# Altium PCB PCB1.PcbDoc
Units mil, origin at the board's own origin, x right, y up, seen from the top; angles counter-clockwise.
Board outline 3785 x 5141 mil, 2 copper layers (Top Layer, Bottom Layer); 51 components, 34 nets, 186 pads, 22 vias.
Unrouted connection lines stored in the file: 92.
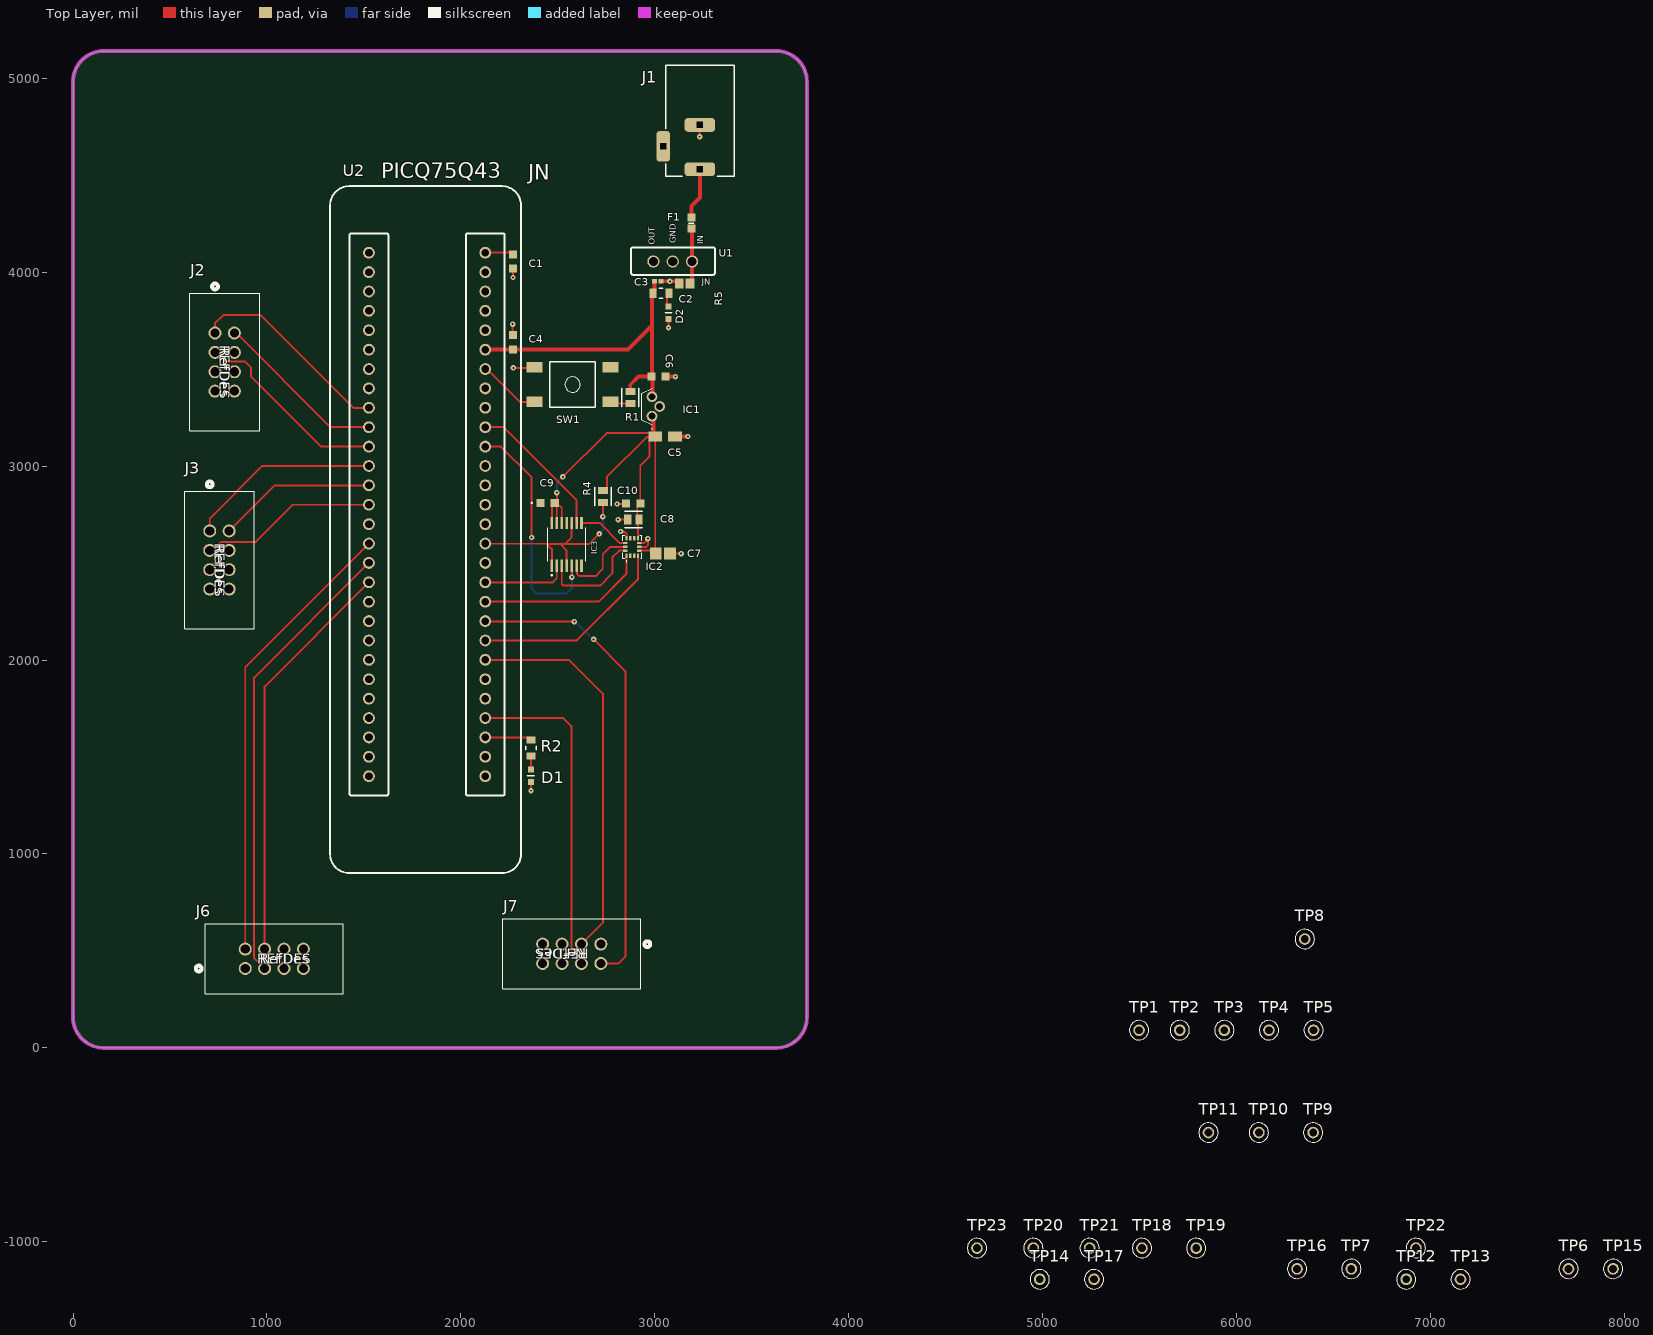
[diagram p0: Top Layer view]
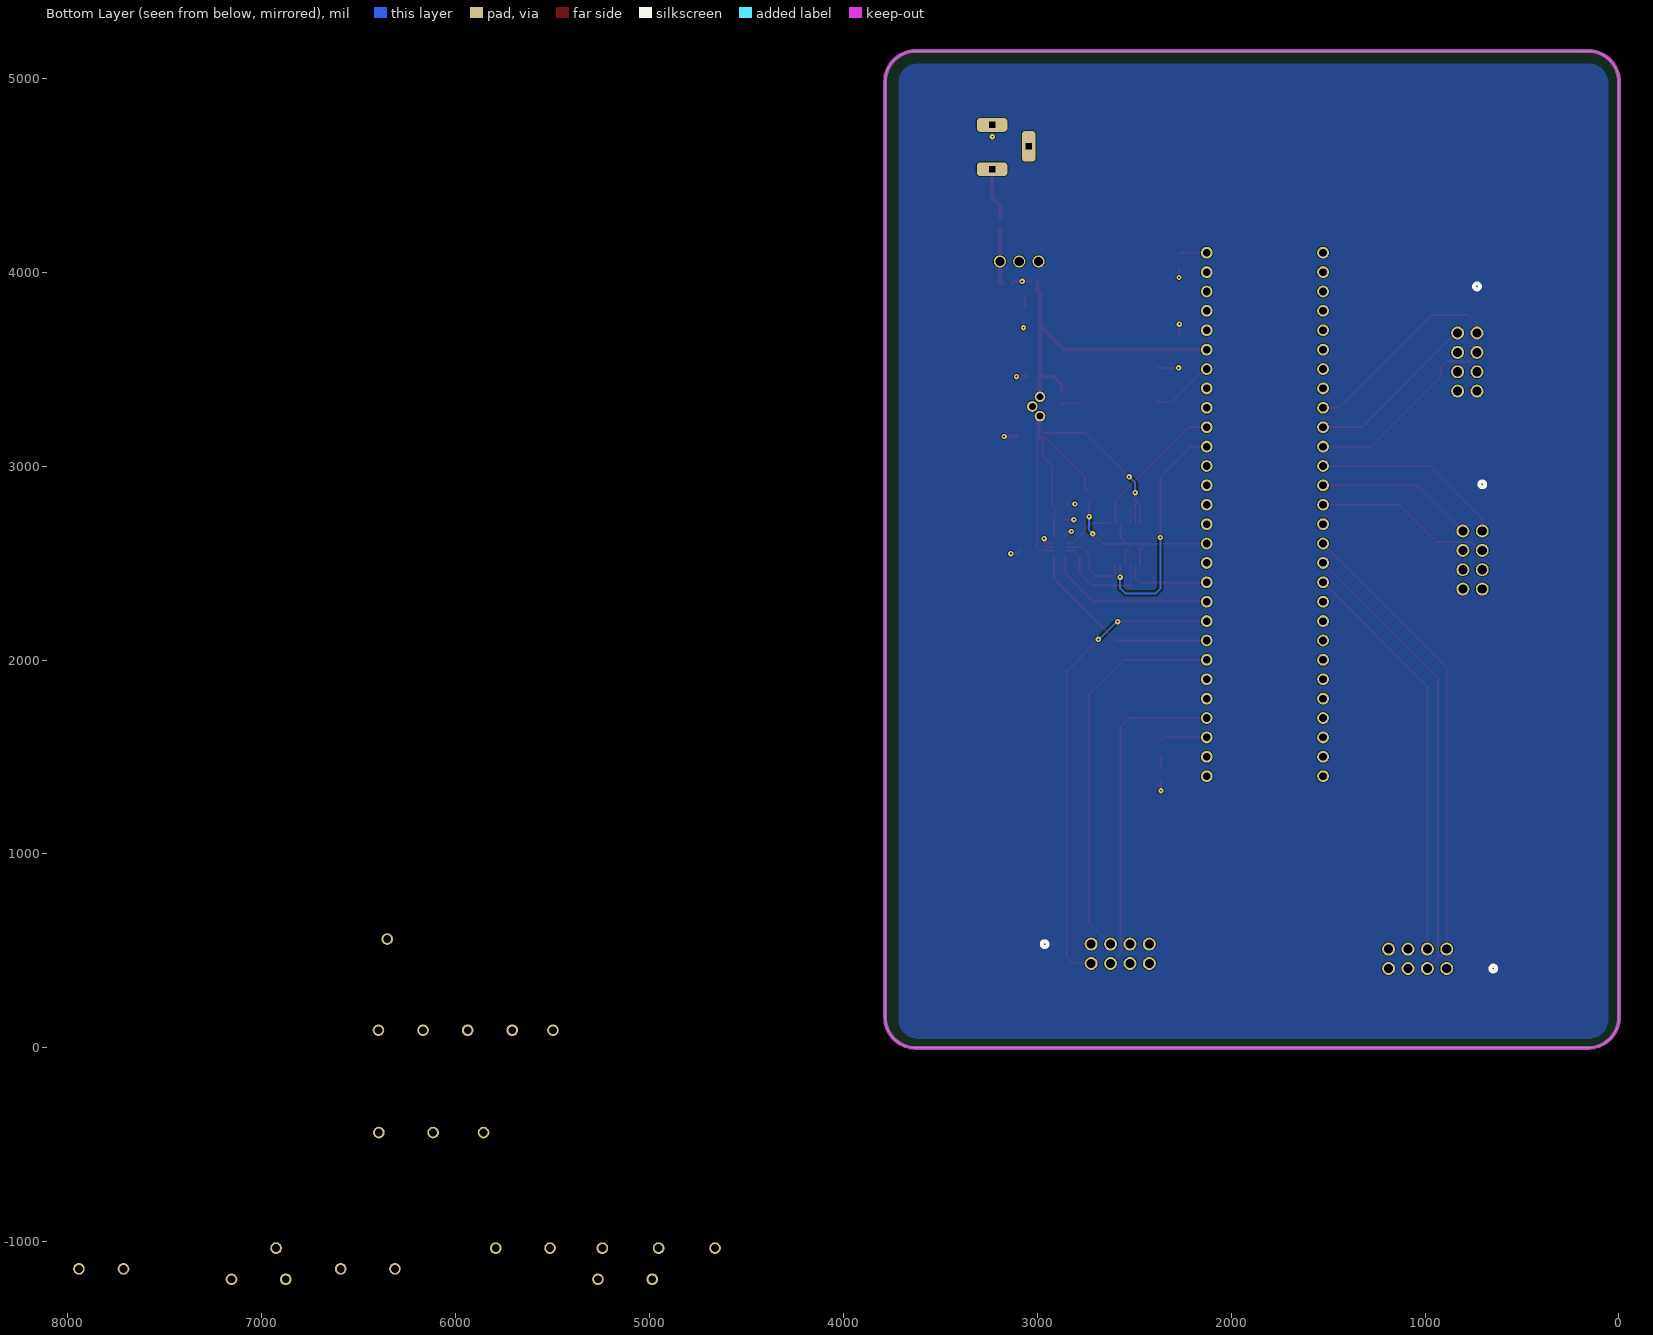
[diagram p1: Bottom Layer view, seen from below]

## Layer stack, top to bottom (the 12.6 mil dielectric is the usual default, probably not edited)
Top Solder: solder mask 0.4, Solder Resist, Dk 3.5
Top Layer: signal copper 1.4
Dielectric 1: dielectric 12.6, FR-4, Dk 4.8
Bottom Layer: signal copper 1.4
Bottom Solder: solder mask 0.4, Solder Resist, Dk 3.5

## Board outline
0,157.48 0,4983.52 cw(c157.48,4983.52) 157.48,5141 3627.52,5141 cw(c3627.52,4983.52) 3785,4983.52 3785,157.48 cw(c3627.52,157.48) 3627.52,0 157.48,0 cw(c157.48,157.48)

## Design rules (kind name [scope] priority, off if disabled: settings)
Clearance PTH_Hole_to_Copper [IsPad and (HoleSize > 0) vs IsPad and (HoleSize > 0)] p1: gap=4 ignorepadtopadclearanceinfootprint=FALSE except(3: SMDPad-Fill SMDPad-Poly SMDPad-Region; 4.02: Via-Hole; 11.81: Fill-Hole Poly-Hole Region-Hole; 13.78: Arc-Hole Track-Hole)
Clearance Via_Hole_to_Copper [IsVia vs IsVia] p2: gap=4 ignorepadtopadclearanceinfootprint=FALSE except(3: SMDPad-Fill SMDPad-Poly SMDPad-Region; 4.02: Arc-Arc Arc-Track Track-Track Via-Fill Via-Poly Via-Region Via-Hole; 7.87: Arc-Hole Track-Hole Fill-Hole Poly-Hole Region-Hole)
Clearance Same_Net_Track [IsTrack vs IsTrack] p3: gap=4 ignorepadtopadclearanceinfootprint=FALSE except(3: SMDPad-Fill SMDPad-Poly SMDPad-Region; 4.02: Via-Hole; 9.84: Arc-Arc Arc-Track Track-Track)
Clearance [All] p4: gap=4 ignorepadtopadclearanceinfootprint=FALSE except(2: Text-Text; 3: SMDPad-Fill SMDPad-Poly SMDPad-Region; 4.02: SMDPad-Text THPad-Text Via-Hole; 5.91: SMDPad-SMDPad; 10: Track-Poly)
ComponentClearance [All] p1: gap=10 collisioncheckmode=3 verticalgap=20 showdistances=FALSE
HoleSize [All] p1: absolutevalues=TRUE maxlimit=248.03 minlimit=5.91 maxpercent=80.000 minpercent=20.000
HoleToHoleClearance Via_Hole_to_Hole [IsVia vs IsVia] p1: gap=7.87 allowstackedmicrovias=TRUE
HoleToHoleClearance Pad_Hole_to_Hole [IsPad vs IsPad] p2: gap=17.72 allowstackedmicrovias=TRUE
MinimumAnnularRing PTH_Annular_Ring [IsPad and (HoleSize > 0)] p1: minimumring=7.87
MinimumAnnularRing Via_Annular_Ring [IsVia] p2: minimumring=2.95
MinimumSolderMaskSliver [All] p1: minsoldermaskwidth=3.94
PolygonConnect [All] p1: connectstyle=Direct reliefconductorwidth=10 reliefentries=4 polygonreliefangle="90 Angle" airgapwidth=10
RoutingVias [All] p1: holewidth=10 width=28 viastyle="Through Hole" minholewidth=5.91 minwidth=11.81 maxholewidth=248.03 maxwidth=259.84
SilkToSolderMaskClearance [IsPad] p1: minsilkscreentomaskgap=5.91 clearancetoexposedcopper=TRUE
SolderMaskExpansion [All] p1: expansion=0 istentingtop=FALSE
SupplyNets "Schematic Supply Nets_8" [InNet('+9V')] p1: voltage=0.000
SupplyNets "Schematic Supply Nets_7" [InNet('+5V_IN')] p2: voltage=0.000
SupplyNets "Schematic Supply Nets_6" [InNet('+5V_BUS')] p3: voltage=0.000
SupplyNets "Schematic Supply Nets_4" [InNet('+3V3')] p4: voltage=0.000
SupplyNets "Schematic Supply Nets_2" [InNet('GND')] p5: voltage=0.000
UnRoutedNet [All] p1: checkbadconnections=TRUE
Width [All] p1: maxlimit=20 minlimit=3.94 preferedwidth=10
24 further rules are at their usual default settings.

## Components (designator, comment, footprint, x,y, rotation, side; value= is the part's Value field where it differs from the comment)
C1 ".1uF 25V" C2012_Commercial 2270,4056 r90 top
C2 ".33uF 35V" CAPC2113X120X50LL20T30 3154,3942 r0 top
C3 ".1uF 25V" CAPC1005X56X25NL10T15 3015.68,3954 r180 top
C4 ".1uF 25V" C2012_Commercial 2269,3639 r270 top
C5 "2.2uF 35V" CAPPM3216X180N 3054,3154 r0 top
C6 "1uF 25V" C2012_Commercial 3020,3463 r180 top
C7 "10nF 50V" CAPC2013X94X50ML20T25 3042,2550 r180 top
C8 "2.2uF 16V" FP-C0805C225K4RACAUTO-MFG 2890,2725 r180 top
C9 ".1uF 25V" C2012_Commercial 2448,2811 r0 top
C10 ".1uF 25V" C2012_Commercial 2889,2807 r0 top
D1 "LED_B" FP-SML-D12-MFG 2361,1404 r90 top
D2 "LED_Y" FP-SML-D12-MFG 3071,3792 r90 top
F1 "1A_FUSE" FUSC1608X61N 3189,4254 r270 top
IC1 "LP2950-33LPRE3" TL431CLPM 2986,3258 r90 top
IC2 "ICM-42688-P" IIM42352 2884,2584 r90 top
IC3 "SN74LVC125APWR" SN74LVC125APWR 2546,2597 r0 top
J1 "694108301002" 694108301002 3233,4781.65 r180 top
J2 "702460801" CONN_7024608xx_MOL 732,3687 r270 top
J3 "702460801" CONN_7024608xx_MOL 705,2666 r270 top
J6 "702460801" CONN_7024608xx_MOL 888,409 r0 top
J7 "702460801" CONN_7024608xx_MOL 2722,535 r180 top
R1 "10k .125W" FP-CRGCQ0805-IPC_C 2874,3354 r90 top value=10KΩ
R2 "562R .125W" FP-RT0805-MFG 2362,1547 r90 top value=562Ω
R4 "10k .125W" FP-CRGCQ0805-IPC_C 2733,2844 r90 top value=10KΩ
R5 "562R  .125W" FP-RT0805-MFG 3032,3892 r180 top value=562Ω
SW1 "Button" FP-1301_9320-MFG 2576,3421 r0 top
TP1 "5001" KEYSTONE_5001 5498,91 r0 top
TP2 "5001" KEYSTONE_5001 5708,91 r0 top
TP3 "5001" KEYSTONE_5001 5938,91 r0 top
TP4 "5001" KEYSTONE_5001 6168,91 r0 top
TP5 "5001" KEYSTONE_5001 6398,91 r0 top
TP6 "5001" KEYSTONE_5001 7713,-1140 r0 top
TP7 "5001" KEYSTONE_5001 6593,-1140 r0 top
TP8 "5001" KEYSTONE_5001 6353,561 r0 top
TP9 "5001" KEYSTONE_5001 6396,-437 r0 top
TP10 "5001" KEYSTONE_5001 6116,-437 r90 top
TP11 "5001" KEYSTONE_5001 5856,-437 r0 top
TP12 "5001" KEYSTONE_5001 6876,-1194 r90 top
TP13 "5001" KEYSTONE_5001 7156,-1194 r90 top
TP14 "5001" KEYSTONE_5001 4986,-1194 r90 top
TP15 "5001" KEYSTONE_5001 7943,-1140 r90 top
TP16 "5001" KEYSTONE_5001 6313,-1140 r90 top
TP17 "5001" KEYSTONE_5001 5266,-1194 r90 top
TP18 "5001" KEYSTONE_5001 5513,-1033 r90 top
TP19 "5001" KEYSTONE_5001 5793,-1033 r90 top
TP20 "5001" KEYSTONE_5001 4953,-1033 r90 top
TP21 "5001" KEYSTONE_5001 5243,-1033 r0 top
TP22 "5001" KEYSTONE_5001 6926,-1033 r90 top
TP23 "5001" KEYSTONE_5001 4662,-1033 r90 top
U1 "LM7805_JN" LM7805_JN 3093,4056 r180 top
U2 "PIC18F57Q43" PIC1857Q43_JN 1326,901 r0 top

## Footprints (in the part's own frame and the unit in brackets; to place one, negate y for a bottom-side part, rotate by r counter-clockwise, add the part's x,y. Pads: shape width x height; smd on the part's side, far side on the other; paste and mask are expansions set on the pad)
694108301002 [mm] "DC Power Jack Right Angled(6.4)"
  rrect50% 4x1.8 hole 0.8 square: 1(0,6.35) 2(0,0.55)
  rrect50% 1.8x4 hole 0.8 square: 3(4.8,3.35)
  silkscreen extent -4.5,-7.25 4.5,7.25, body extent -4.5,-7.25 5,7.25, height 10.75
C2012_Commercial [mm]
  rect 1.05x1.05 smd: 1(-0.925,0) 2(0.925,0)
  body extent -0.96,-0.8 1.04,0.8, height 1.25
CAPC1005X56X25NL10T15 [mm] "Chip Capacitor, 2-Leads, Body 1.00x0.50mm, IPC Medium Density"
  rect 0.68x0.64 smd: 1(-0.44,0) 2(0.44,0)
  body extent -0.55,-0.3 0.55,0.3, height 0.56
CAPC2013X94X50ML20T25 [mm] "Chip Capacitor, 2-Leads, Body 2.01x1.25mm, IPC Low Density"
  rect 1.55x1.55 smd: 1(-0.925,0) 2(0.925,0)
  body extent -1.1,-0.72 1.11,0.72, height 0.94
CAPC2113X120X50LL20T30 [mm] "Chip Capacitor, 2-Leads, Body 2.05x1.25mm, IPC High Density"
  rect 1.15x1.35 smd: 1(-0.7,0) 2(0.7,0)
  body extent -1.13,-0.72 1.12,0.72, height 1.2
CAPPM3216X180N [mm]
  rect 1.8x1.3 smd: 1(-1.3,0) 2(1.3,0)
  body extent -1.6,-0.82 1.6,0.82, height 1.8
CONN_7024608xx_MOL [mil]
  round 67 / inner round 60 / far side round 67 hole 47 paste-99999 mask+0: 1(0,0) 2(0,100) 3(100,0) 4(100,100) 5(200,0) 6(200,100) 7(300,0) 8(300,100)
  silkscreen extent -255,-130 505,230
FP-1301_9320-MFG [mm]
  rect 2.1x1.4 smd paste+0 mask+0: 1(-5,2.25) 2(5,2.25) 3(-5,-2.25) 4(5,-2.25)
  silkscreen extent -3,-3 3,3, body extent -6.15,-3.1 6.15,3.1, height 0.25
FP-C0805C225K4RACAUTO-MFG [mm]
  rect 0.95x1.35 smd paste+0 mask+0: 1(-0.75,0) 2(0.75,0)
  silkscreen extent -1.15,-1.07 1.15,1.07, body extent -1.4,-0.85 1.4,0.85, height 0.25
FP-CRGCQ0805-IPC_C [mil]
  rect 35.67x51.57 smd paste+0 mask+0: 1(-30.55,0) 2(30.55,0)
  silkscreen extent -48,-43 48,43, body extent -52,-31 52,31, height 10
FP-RT0805-MFG [mm]
  rect 0.9x1.2 smd paste+0 mask+0: 1(-1.05,0) 2(1.05,0)
  silkscreen extent -0.23,-0.67 0.23,0.67, body extent -1.6,-0.77 1.6,0.77, height 0.25
FP-SML-D12-MFG [mm]
  rect 0.8x0.8 smd paste+0 mask+0: 1(-0.825,0) 2(0.825,0)
  silkscreen extent 0,-0.45 0,0.45, body extent -1.33,-0.55 1.33,0.55, height 0.25
FUSC1608X61N [mm]
  rect 1x1.02 smd: 1(-0.72,0) 2(0.72,0)
  silkscreen extent 0,-0.33 0,0.33, body extent -0.79,-0.43 0.79,0.43, height 0.61
IIM42352 [mm]
  rect 0.6x0.3 smd: 1(-1.15,0.75) 2(-1.15,0.25) 3(-1.15,-0.25) 4(-1.15,-0.75) 8(1.15,-0.75) 9(1.15,-0.25) 10(1.15,0.25) 11(1.15,0.75)
  rect 0.3x0.6 smd: 5(-0.5,-0.9) 6(0,-0.9) 7(0.5,-0.9) 12(0.5,0.9) 13(0,0.9) 14(-0.5,0.9)
  silkscreen extent -1.95,-1.25 1.5,1.25, body extent -1.5,-1.25 1.5,1.25, height 0.9
KEYSTONE_5001 [mm]
  round 1.53 hole 1.02: TP(0,0)
  silkscreen extent -1.27,-1.27 1.27,1.27, body extent -1.27,-1.27 1.27,1.27, height 4.57
LM7805_JN [mm]
  round 1.6 hole 1.2 paste-2539.97 mask+0.1: 1(-2.54,0) 2(0,0) 3(2.54,0)
  silkscreen extent -5.54,-1.85 5.46,1.75
PIC1857Q43_JN [mm]
  round 1.55 hole 1 paste-2539.97 mask+0.1: 1(5.08,81.28) 2(5.08,78.74) 3(5.08,76.2) 4(5.08,73.66) 5(5.08,71.12) 6(5.08,68.58) 7(5.08,66.04) 8(5.08,63.5) 9(5.08,60.96) 10(5.08,58.42) 11(5.08,55.88) 12(5.08,53.34) 13(5.08,50.8) 14(5.08,48.26) 15(5.08,45.72) 16(5.08,43.18) 17(5.08,40.64) 18(5.08,38.1) 19(5.08,35.56) 20(5.08,33.02) 21(5.08,30.48) 22(5.08,27.94) 23(5.08,25.4) 24(5.08,22.86) 25(5.08,20.32) 26(5.08,17.78) 27(5.08,15.24) 28(5.08,12.7) 29(20.32,81.28) 30(20.32,78.74) 31(20.32,76.2) 32(20.32,73.66) 33(20.32,71.12) 34(20.32,68.58) 35(20.32,66.04) 36(20.32,63.5) 37(20.32,60.96) 38(20.32,58.42) 39(20.32,55.88) 40(20.32,53.34) 41(20.32,50.8) 42(20.32,48.26) 43(20.32,45.72) 44(20.32,43.18) 45(20.32,40.64) 46(20.32,38.1) 47(20.32,35.56) 48(20.32,33.02) 49(20.32,30.48) 50(20.32,27.94) 51(20.32,25.4) 52(20.32,22.86) 53(20.32,20.32) 54(20.32,17.78) 55(20.32,15.24) 56(20.32,12.7)
  silkscreen extent 0,0 25,90
SN74LVC125APWR [mm]
  rect 0.35x1.6 smd: 1(-1.95,-2.8) 2(-1.3,-2.8) 3(-0.65,-2.8) 4(0,-2.8) 5(0.65,-2.8) 6(1.3,-2.8) 7(1.95,-2.8) 8(1.95,2.8) 9(1.3,2.8) 10(0.65,2.8) 11(0,2.8) 12(-0.65,2.8) 13(-1.3,2.8) 14(-1.95,2.8)
  silkscreen extent -2.5,-4.1 2.5,2.2, body extent -2.5,-3.2 2.5,3.2, height 1.13
TL431CLPM [mm]
  round 1.4 hole 0.9: 1(0,0) 2(1.27,-1) 3(2.54,0)
  silkscreen extent -1.71,-0.05 3.67,1.35, body extent -1.13,-2.22 3.69,1.46, height 9.91

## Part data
C1 C4 C9 C10: library part C2012X7R1V105K085AB, "Capacitor / C0805C104J3RACTU / 0805", Manufacturer_Name=TDK, Mouser Part Number=810-C2012X7R1V105K0B
C2: library part CMP-2007-04070-1, "TAJR334K035RNJ", Manufacturer="AVX Interconnect / Elco"
C3: library part CMP-1034-02072-2, "04023D104KAT2A", Manufacturer="AVX Interconnect / Elco"
C5: library part TPSA225K035R1500, "Capacitor Polarised / 1.5ohm ESR for Output Requirement / Tantalum / 1206", Manufacturer_Name="Kyocera AVX", Mouser Part Number=581-TPSA225K035R1500
C6: library part C2012X7R1V105K085AB, "Capacitor / C0805C105K3RACTU / 0805", Manufacturer_Name=TDK, Mouser Part Number=810-C2012X7R1V105K0B
C7: library part CMP-2007-04453-1, "KGM21NR71H103KT /  / 0805", Manufacturer="AVX Interconnect / Elco", Part Number=0805YC103MAT2A
C8: library part CMP-2007-03267-2, "CAP CER 2.2UF 16V X7R 0805 / C0805C225K4RACAUTO", Capacitance=2.2uF, Case Code (Imperial)=0805, Case Code (Metric)=2012, Dielectric=X7R, Dielectric Material=Ceramic, Max Operating Temperature=125°C, Min Operating Temperature=-55°C, Package Quantity=1, Ratings=AEC-Q200, Tolerance=10%, Voltage Rating=16V
D1: library part CMP-08952-000023-1, "SMLD12BN1WT86 /  / BLUE LED 0603", Colour=Yellow, Forward Current=20mA, Forward Voltage=2.2V, Manufacturer=Rohm, Manufacturer Part Number=SML-D12Y8WT86, Package=SML-D12, Power Dissipation=54mW, Reverse Voltage=5V, Temperature="-40°C to +85°C", Temperature Range High=+85°C, Temperature Range Low=-40°C
D2: library part CMP-08952-000023-1, "LED YELLOW DIFFUSED 0603 SMD / SML-D12Y8WT86", Colour=Yellow, Forward Current=20mA, Forward Voltage=2.2V, Manufacturer=Rohm, Manufacturer Part Number=SML-D12Y8WT86, Package=SML-D12, Power Dissipation=54mW, Reverse Voltage=5V, Temperature="-40°C to +85°C", Temperature Range High=+85°C, Temperature Range Low=-40°C
F1: library part 0438001.A, "Fuse", Manufacturer_Name=LITTELFUSE
IC1: "Integrated Circuit", Manufacturer_Name="Texas Instruments", Mouser Part Number=595-LP2950-33LPRE3
IC2: "Integrated Circuit", Manufacturer_Name=TDK, Mouser Part Number=410-ICM-42688-P
IC3: "Integrated Circuit", Manufacturer_Name="Texas Instruments", Mouser Part Number=595-SN74LVC125APWR
J1: library part CMP-1502-00190-4, "DC Power Jack Connector WR-DC, Male, Right Angled, THT, 5 A, 24 V", Color=Black, Current Rating=5A, Flammability Rating="UL94 V-0", Insulation Resistance=100MΩ, Max Operating Temperature=85°C, Min Operating Temperature=-40°C, Operating Supply Voltage=24V, Voltage Rating=30V
J2 J3 J6 J7: "2.54mm Pitch C-Grid Header, Low Profile, Dual Row, Vertical, Shrouded, 8  Circuits, 0.38Âµm Gold (Au) Selective Plating", Manufacturer_Name="Molex Connector Corporation"
R1 R4: library part CMP-03211-002989-1, "CRGCQ0805J10K", Ambient Temperature Range High=+70°C, Manufacturer="TE Connectivity", Package=CRGCQ0805, Power Rating=0.125W, Resistance=10KΩ, Temperature="-55°C to +155°C", Temperature Coefficient=±100ppm/°C, Temperature Range High=+155°C, Temperature Range Low=-55°C, Tolerance=0.05, Voltage Rating=150V
R2 R5: library part CMP-03412-035770-1, "RES SMD 562 OHM 1% 1/8W 0805 / RT0805FRD07562RL", Manufacturer=Yageo, Manufacturer Part Number=RT0805FRD07562RL, Package=RT0805, Power Rating=0.125W, Resistance=562Ω, Temperature="-55°C to +155°C", Temperature Coefficient="25 ppm/°C", Temperature Range High=+155°C, Temperature Range Low=-55°C, Tolerance=0.0001, Voltage Rating=150V
SW1: library part CMP-26321-000001-1, "SWITCH TACTILE SPST-NO 0.05A 12V / 1301.9320", Contact Current Rating=50mA, Contact Resistance=100mΩ, Manufacturer=Schurter, Manufacturer Part Number=1301.9320, Operating Force=1.6N, Package=0, Temperature="-20°C to +70°C", Temperature Range High=+70°C, Temperature Range Low=-20°C, Voltage Rating Dc=12V
TP1 TP2 TP3 TP4 TP5 TP6 TP7 TP8 TP9 TP10 TP11 TP12 TP13 TP14 TP15 TP16 TP17 TP18 TP19 TP20 TP21 TP22 TP23: library part CMP-003-000000-1, Package=None
U1: library part LM7805_JN_1
U2: library part PIC18F57Q43_JN

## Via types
v1: diameter 28, hole 10, Top Layer to Bottom Layer, 22 vias

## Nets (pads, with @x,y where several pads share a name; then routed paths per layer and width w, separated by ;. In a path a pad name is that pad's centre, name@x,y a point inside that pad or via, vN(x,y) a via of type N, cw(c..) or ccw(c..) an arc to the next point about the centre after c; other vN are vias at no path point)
+3V3: C5.1 C7.2 C8.1 C9.2 C10.2 IC1.1 IC2.5 IC2.8 IC3.12 IC3.13 IC3.14 R4.2 TP6.TP | length 3224.6
  Top Layer w10: 2122,2401 2475,2401 2494.82,2420.82 2494.82,2486.76 ; IC3.14 2469.23,2794.81 C9.2@2485.42,2811 ; C9.2@2493.82,2801.6 C9.2 2495,2821.58 v1(2495,2864) ; IC3.13 2494.82,2801.6 2500.5,2795.91 2511.09,2795.91 2520.41,2786.59 IC3.12 ; v1(2526,2945) 2752,3171 C5.1@2971.83,3171 ; R4.2 2740.95,2874.55 2753.78,2887.39 2753.78,2944.78 2958.36,3149.36 2988.99,3149.36 2993.63,3154 C5.1 ; C8.1@2909.75,2748 2909.75,2791.33 C10.2 2925.42,3002.42 2972.39,3049.39 2972.39,3133.41 C5.1@2980.6,3141.63 ; IC2.8 C8.1@2913.53,2725 ; IC2.5 2987.9,2564.31 C7.2@2996.58,2573 ; C5.1@2992.98,3154 C5.1@2980.6,3141.63 ; C7.2@3002.82,2576 C5.1 ; C5.1@2980.6,3141.63 2990.45,3141.63 C5.1
  Top Layer w20: IC1.1@2993.63,3266 2993.63,3163.19 C5.1
  Bottom Layer w10: v1@2496,2864 2495,2865 2495,2914 v1(2526,2945)
+5V_BUS: C1.2 TP15.TP U2.29 | length 147.6
  Top Layer w10: U2.29 2261.42,4101 C1.2
+5V_IN: C3.2 C4.2 C6.2 IC1.3 R1.2 R5.2 U1.3 U2.34 | length 1673.1
  Top Layer w20: U2.34 2862.62,3601 2986.62,3725 ; R1.2 2874,3420 2917,3463 C6.2 ; IC1.3@2993.63,3366 2988.61,3371.02 2988.61,3457.98 C6.2 ; C3.2 2998.35,3899.69 R5.2 2986.62,3887.96 2986.62,3725 ; C6.2 2986.62,3466.04 2986.62,3725
+9V: F1.1 J1.1 TP22.TP | length 267.5
  Top Layer w20: F1.1 3189,4341.53 3233,4385.53 J1.1
BUT_D: SW1.3 TP23.TP U2.35 | length 323.3
  Top Layer w10: U2.35 2136,3501 2305,3332 2378.73,3332 SW1.3
GND: C1.1 C2.1 C3.1 C4.1 C5.2 C6.1 C7.1 C8.2 C9.1 C10.1 D1.1 D2.1 IC1.2 IC2.6 IC2.7 IC2.11 IC3.7 J1.2 J2.8 J3.8 J6.8 J7.8 SW1.1 TP7.TP TP8.TP TP14.TP TP16.TP TP17.TP U1.2 U2.15 U2.24 U2.30 U2.33 U2.43 U2.52 | length 948.5
  Top Layer w10: v1(2267,3733) 2267,3677.42 C4.1 ; v1(2269,3973) 2269,4018.58 C1.1 ; v1(2271,3507) 2376.57,3507 SW1.1 ; D1.1 2362,1370.52 v1(2362,1326) ; v1@2800,2805 2850.58,2805 C10.1 ; v1(2811,2724) 2859.47,2724 C8.2 ; v1(2824,2663) 2827.44,2659.56 2846.44,2659.56 2854.47,2651.53 IC2.11 ; IC2.6 2957,2584 2965,2592 v1(2965,2626) 2942.69,2603.69 IC2.7 ; v1(3071.09,3714.09) D2.1@3071.09,3759.43 ; C7.1@3078.42,2572 3101.42,2549 v1(3136,2549) ; v1(3232,4699) 3232,4759 J1.2
  Top Layer w20: C3.1 3114.44,3954 C2.1 ; C6.1 3056.92,3462.5 3106.5,3462.5 v1(3107,3462) ; C5.2 3105.68,3153.5 3170.5,3153.5 v1(3171,3153)
  other v1: 2806,2805 3078,3953
GPIO1: J7.2 TP13.TP U2.48 | length 2444.5
  Top Layer w10: U2.48 2127.5,2199.5 2584.5,2199.5 v1(2586,2198) ; v1(2685,2107) 2849,1943 2849,469.81 2814.19,435 J7.2
  Bottom Layer w10: v1(2586,2198) 2590,2198 2681,2107 v1(2685,2107)
GPIO2: J7.3 TP19.TP U2.50 | length 2015.9
  Top Layer w10: U2.50 2557,2001 2733,1825 2733,646 J7.3
GPIO3: J7.4 TP21.TP U2.53 | length 1706.9
  Top Layer w10: U2.53 2528,1701 2570,1659 2570,487 J7.4
GPIO4: J6.2 TP12.TP U2.16 | length 2356.3
  Top Layer w10: J6.2 888,1963 U2.16
GPIO5: J6.3 TP18.TP U2.17 | length 2359.6
  Top Layer w10: J6.3 934,463 934,1909 U2.17
GPIO6: J6.4 TP20.TP U2.18 | length 2114.8
  Top Layer w10: J6.4 988,1863 U2.18
IMU_CLK: IC2.13 IC3.6 TP2.TP | length 403.5
  Top Layer w10: IC3.6 2599.07,2484.87 2599.07,2444.93 2611,2433 2695,2433 2732,2470 2732,2545 2771,2584 IC2.13
IMU_SDI: IC2.14 IC3.3 TP3.TP | length 549.2
  Top Layer w10: IC3.3 2520.41,2391.59 2528,2384 2718,2384 2782,2448 2782,2530 2816.31,2564.31 IC2.14
IMU_SS: IC2.12 IC3.8 TP1.TP | length 268.7
  Top Layer w10: IC3.8 2715.76,2707.24 2819.31,2603.69 IC2.12
INT1: IC2.4 TP5.TP U2.49 | length 1041
  Top Layer w10: U2.49 2599,2101 2913.53,2415.53 IC2.4
LED_D: R2.2 U2.54 | length 241.2
  Top Layer w10: U2.54 2349.34,1601 R2.2
LLS_EN: IC3.1 IC3.4 IC3.10 R4.1 U2.44 | length 1154.3
  Top Layer w10: U2.44@2123,2600 2441,2600 2469.23,2571.77 IC3.1 ; U2.44 U2.44@2127,2600 ; 2442,2599 2512,2599 ; 2539.71,2600.71 2571.59,2632.59 IC3.10 ; IC3.4 2546,2565 2512,2599 ; v1(2714,2651) 2662,2599 2512,2599 ; v1(2733,2740) R4.1
  Bottom Layer w10: v1(2714,2651) 2733,2670 v1(2733,2740)
NetC2_2: C2.2 F1.2 U1.1 | length 290
  Top Layer w20: C2.2 3193,3953.44 U1.1 3193,4221.65 F1.2
NetD1_2: D1.2 R2.1 | length 68.2
  Top Layer w10: D1.2@2362,1437.48 R2.1
NetD2_2: D2.2 R5.1 | length 51.9
  Top Layer w10: D2.2@3062.93,3821.45 R5.1@3062.93,3873.38
NetR1_1: R1.1 SW1.4 | length 104.9
  Top Layer w10: SW1.4 2781.82,3323.45 R1.1
RB1: J2.2 U2.10 | length 895.3
  Top Layer w10: J2.2 841,3687 1327,3201 U2.10
RB2: J2.1 U2.9 | length 1058.8
  Top Layer w10: J2.1 732,3736 775,3779 968,3779 1446,3301 U2.9
RC4: J2.3 U2.11 | length 1026.4
  Top Layer w10: J2.3 732,3580 771,3541 885,3541 918,3508 918,3462 1279,3101 U2.11
RC5: J3.1 U2.12 | length 997.3
  Top Layer w10: J3.1 705,2730 976,3001 U2.12
RC6: J3.2 U2.13 | length 818.3
  Top Layer w10: J3.2 1040,2901 U2.13
RD4: J3.3 U2.14 | length 918.3
  Top Layer w10: J3.3 720,2566 764,2610 943,2610 1134,2801 U2.14
RX: U2.26
SPI2_CLK: IC3.5 TP10.TP U2.39 | length 1224.9
  Top Layer w10: U2.39 2207,3101 2365,2943 v1(2365,2632) ; IC3.5 2572.3,2486.06 2572.3,2428.7 v1(2573,2428)
  Bottom Layer w10: v1(2365,2632) 2365,2369 2390,2344 2547,2344 2573,2370 v1(2573,2428)
SPI2_SDI: IC2.1 TP4.TP | length 882.2
  Top Layer w10: 2126,2301 2711,2301 2854.47,2444.47 IC2.1
SPI2_SDO: IC3.2 TP9.TP
SPI2_SS: IC3.9 TP11.TP U2.38 | length 744.6
  Top Layer w10: U2.38 2221,3201 2597.18,2824.82 IC3.9
TX: U2.25
pads on no net: IC2.2 IC2.3 IC2.9 IC2.10 IC3.11 J1.3 J2.4 J2.5 J2.6 J2.7 J3.4 J3.5 J3.6 J3.7 J6.1 J6.5 J6.6 J6.7 J7.1 J7.5 J7.6 J7.7 SW1.2 U2.1 U2.2 U2.3 U2.4 U2.5 U2.6 U2.7 U2.8 U2.19 U2.20 U2.21 U2.22 U2.23 U2.27 U2.28 U2.31 U2.32 U2.36 U2.37 U2.40 U2.41 U2.42 U2.45 U2.46 U2.47 U2.51 U2.55 U2.56

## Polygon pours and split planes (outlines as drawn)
no net on Bottom Layer "NONET_L02_P000" (solid, pour order 0): 3614.86,5076 cw(c3615,4976) 3715,4976 3715,147 cw(c3615,147) 3615,47 156,47 cw(c156,147) 56,147 56,4976 cw(c156,4976) 156,5076

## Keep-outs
Keep-Out Layer:
  the board outline again, w20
